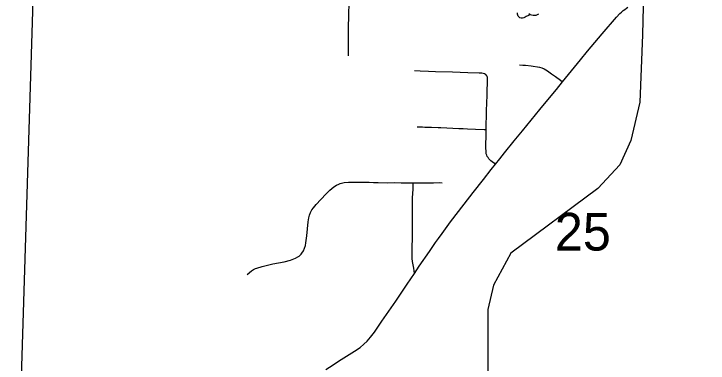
# Model space of a CAD drawing. Extents: x -59 to 43, y 0 to 22.
# Drawn here: x 24.147 to 24.918, y 16.594 to 16.982 of the extents above; entities that cross this region are included whole.
import ezdxf

# ---------------------------------------------------------------- set-up
doc = ezdxf.new("R2010")
doc.units = 0
for name, color, linetype in [('Default', 7, 'Continuous'), ('GM_X_City_Street', 7, 'Continuous'), ('GM_X_County_Road', 7, 'Continuous'), ('GM_X_Rail_Line', 7, 'Continuous'), ('GM_X_Section', 7, 'Continuous'), ('GM_X_Section_Text', 7, 'Continuous')]:
    doc.layers.add(name, color=color, linetype=linetype)

msp = doc.modelspace()

# ---------------------------------------------------------------- linework, layer by layer
at = {"layer": 'Default'}
msp.add_lwpolyline([(23.51667, 17.35203), (23.51667, 16.35874), (24.14766, 16.33962), (24.1786, 17.34343), (23.63449, 17.34676)], close=True, dxfattribs=at)
at = {"layer": 'GM_X_City_Street'}
for points in [[(24.51847, 16.93533), (24.51848, 16.95362), (24.51837, 16.96493), (24.5188, 16.98152), (24.51902, 16.99351)], [(24.71978, 16.98103), (24.71817, 16.98022), (24.71561, 16.97891), (24.71443, 16.97832), (24.71312, 16.97773), (24.71157, 16.97719), (24.71004, 16.97715), (24.70885, 16.97753), (24.7078, 16.97833), (24.70695, 16.97934), (24.70639, 16.98048), (24.70612, 16.98178), (24.70609, 16.98318)], [(24.71863, 16.98234), (24.72, 16.98126), (24.72167, 16.98082), (24.72335, 16.98049), (24.72506, 16.98045), (24.72675, 16.9807), (24.72839, 16.98123), (24.72989, 16.98203)], [(24.70817, 16.92528), (24.71207, 16.92511), (24.71511, 16.92495), (24.72129, 16.92433), (24.73038, 16.92286), (24.7332, 16.92204), (24.73578, 16.92086), (24.73951, 16.91858), (24.7438, 16.91548), (24.7482, 16.91231), (24.75374, 16.90831), (24.75626, 16.90649)], [(24.5916, 16.91925), (24.59778, 16.91891), (24.60712, 16.91843), (24.61492, 16.91804), (24.63372, 16.91775), (24.6509, 16.91704), (24.66339, 16.91669), (24.66642, 16.9164), (24.66928, 16.91577), (24.67043, 16.91513), (24.67106, 16.91456)], [(24.68161, 16.81501), (24.67778, 16.81777), (24.67631, 16.81884), (24.67531, 16.81977), (24.67425, 16.82104), (24.67332, 16.82243), (24.67253, 16.82376), (24.67191, 16.82517), (24.67142, 16.82661), (24.67112, 16.82928), (24.67095, 16.83323), (24.67095, 16.83882), (24.67119, 16.84433), (24.67134, 16.85363), (24.67175, 16.87429), (24.67202, 16.88311), (24.6724, 16.89134), (24.67256, 16.89866), (24.67282, 16.90343), (24.67289, 16.90795), (24.67275, 16.91174), (24.67207, 16.91338), (24.67106, 16.91456)], [(24.59476, 16.85673), (24.5978, 16.85649), (24.60043, 16.85641), (24.60315, 16.85633), (24.60754, 16.85616), (24.61045, 16.85609), (24.61788, 16.85582), (24.62091, 16.85567), (24.64088, 16.85471), (24.64561, 16.8546), (24.65038, 16.85444), (24.65934, 16.85403), (24.66897, 16.85371), (24.67134, 16.85363)], [(24.40585, 16.69247), (24.41054, 16.69654), (24.41263, 16.69802), (24.4149, 16.69914), (24.41636, 16.69967), (24.4223, 16.70149), (24.43441, 16.70436), (24.44665, 16.70664), (24.45371, 16.70865), (24.45766, 16.70988), (24.45941, 16.71078), (24.46208, 16.71214), (24.46331, 16.713), (24.46448, 16.71397), (24.46555, 16.71509), (24.46652, 16.7163), (24.46817, 16.71894), (24.46946, 16.72177), (24.47038, 16.72474), (24.47097, 16.72779), (24.47189, 16.73552), (24.47358, 16.75097), (24.47425, 16.75558), (24.47503, 16.75859), (24.47615, 16.76149), (24.47765, 16.7642), (24.47947, 16.76673), (24.48249, 16.77028), (24.493, 16.78175), (24.49747, 16.78605), (24.50217, 16.7901), (24.5048, 16.79174), (24.50762, 16.79301), (24.5091, 16.79344), (24.51364, 16.79455), (24.5182, 16.79516), (24.52264, 16.79517), (24.52782, 16.79504), (24.53516, 16.79506), (24.54138, 16.79493), (24.54605, 16.79469), (24.55139, 16.79468), (24.56146, 16.79446), (24.56896, 16.79455), (24.57674, 16.7943), (24.58192, 16.7943), (24.58611, 16.79418), (24.59005, 16.79419), (24.5916, 16.79419), (24.59448, 16.79427), (24.60044, 16.7945), (24.60474, 16.79432), (24.60943, 16.79444), (24.61288, 16.79444), (24.61895, 16.79456), (24.62251, 16.79445)], [(24.59171, 16.69381), (24.5908, 16.69941), (24.58956, 16.70709), (24.58918, 16.71027), (24.58894, 16.7197), (24.58934, 16.73632), (24.58934, 16.74508), (24.58934, 16.75137), (24.58946, 16.76087), (24.58957, 16.77778), (24.59003, 16.78737), (24.59004, 16.79045), (24.59005, 16.79419)]]:
    msp.add_lwpolyline(points, dxfattribs=at)
at = {"layer": 'GM_X_County_Road'}
for points in [[(24.75626, 16.90649), (24.77625, 16.93083), (24.78396, 16.94048), (24.8003, 16.96), (24.81604, 16.9784), (24.81985, 16.9824), (24.82162, 16.98406), (24.8235, 16.98562), (24.82538, 16.98705), (24.82707, 16.98828), (24.82858, 16.98934)], [(24.68161, 16.81501), (24.68645, 16.82115), (24.69167, 16.82754), (24.70255, 16.84097), (24.71157, 16.85206), (24.73091, 16.87582), (24.74348, 16.89103), (24.74943, 16.89818), (24.75626, 16.90649)], [(24.59171, 16.69381), (24.59698, 16.70163), (24.60815, 16.71823), (24.61501, 16.72803), (24.61826, 16.73254), (24.62223, 16.73808), (24.63171, 16.75114), (24.64688, 16.7708), (24.65684, 16.78352), (24.66827, 16.79812), (24.67697, 16.80914), (24.68161, 16.81501)], [(24.49311, 16.58689), (24.49717, 16.58956), (24.51019, 16.598), (24.52495, 16.6073), (24.53109, 16.61163), (24.53552, 16.61517), (24.53916, 16.61865), (24.5429, 16.62292), (24.54708, 16.6284), (24.55551, 16.64076), (24.5631, 16.6517), (24.57081, 16.66279), (24.58357, 16.68172), (24.59171, 16.69381)]]:
    msp.add_lwpolyline(points, dxfattribs=at)
at = {"layer": 'GM_X_Rail_Line'}
msp.add_lwpolyline([(24.85953, 17.57035), (24.84503, 16.95877), (24.842, 16.88397), (24.8319, 16.84152), (24.81977, 16.81423), (24.79552, 16.78795), (24.69852, 16.71618), (24.67932, 16.68081), (24.67326, 16.65352), (24.67326, 15.78932), (24.65978, 15.33239), (24.65406, 14.78664), (24.64437, 14.1)], dxfattribs=at)
at = {"layer": 'GM_X_Section'}
msp.add_lwpolyline([(24.1786, 17.34343), (24.42943, 17.3409), (25.18772, 17.31279), (25.18784, 17.29346), (25.17305, 16.308), (24.14766, 16.33962)], close=True, dxfattribs=at)

# ---------------------------------------------------------------- texts
at = {"layer": 'GM_X_Section_Text'}
msp.add_text('25', height=0.041856, rotation=0.00001, dxfattribs=at).set_placement((24.74756, 16.71916))

doc.saveas('drawing.dxf')
